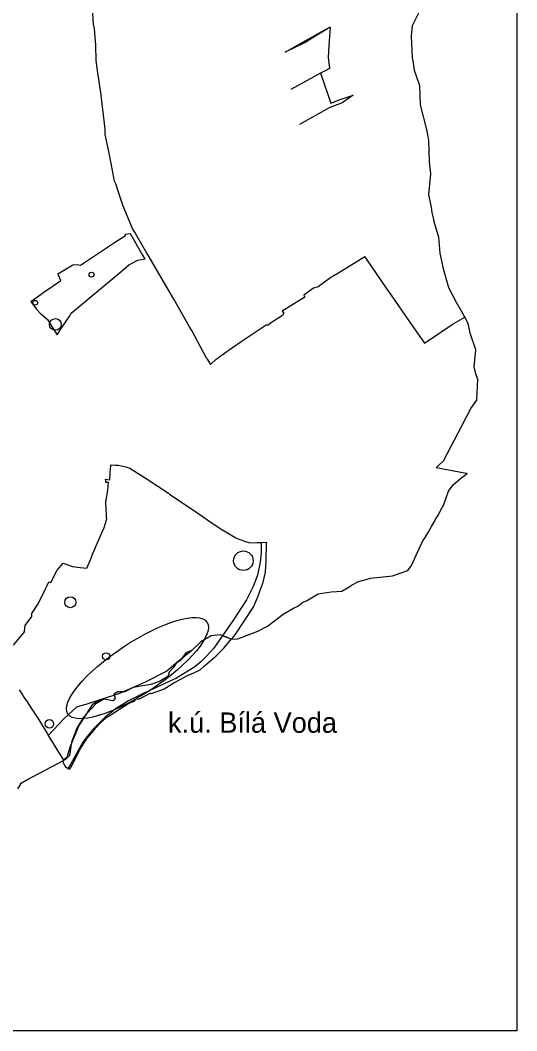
# Model space of a CAD drawing. Extents: x -581323 to -577255, y -1071205 to -1065973.
# Drawn here: x -578420 to -577319, y -1071165 to -1068923 of the extents above; entities that cross this region are included whole.
import ezdxf

# ---------------------------------------------------------------- set-up
doc = ezdxf.new("R2010")
doc.units = 0
for name, color, linetype in [('Budovy', 7, 'Continuous'), ('Hranice katastrálních území', 7, 'Continuous'), ('Lokality vhodné pro vodní komponenty', 7, 'Continuous'), ('Názvy KU', 7, 'Continuous'), ('Popis tisku', 7, 'Continuous'), ('Vnitřní obvod KoPÚ', 7, 'Continuous'), ('Vnější obvod_hranice převzatá z KoPÚ Bílá Voda', 7, 'Continuous'), ('Zbořeniště', 7, 'Continuous'), ('Šetření hranic v lesích', 7, 'Continuous'), ('Šetření řeky_potoky - linie', 7, 'Continuous'), ('Železnice - linie', 7, 'Continuous')]:
    doc.layers.add(name, color=color, linetype=linetype)

msp = doc.modelspace()

# ---------------------------------------------------------------- linework, layer by layer
at = {"layer": 'Budovy'}
for centre, radius in [((-578342.4, -1069598), 13), ((-577925.6, -1070122.3), 21.7), ((-578309.3, -1070214.4), 12.3), ((-578355.7, -1070484.1), 9.44)]:
    msp.add_circle(centre, radius, dxfattribs=at)
at = {"layer": 'Hranice katastrálních území'}
for p, q in [((-577427.3, -1069595.6), (-577434.8, -1069581.8)), ((-577422.8, -1069617.2), (-577427.3, -1069595.6)), ((-577410.1, -1069654.2), (-577422.8, -1069617.2)), ((-577413.8, -1069691.7), (-577410.1, -1069654.2)), ((-577410, -1069707.6), (-577413.8, -1069691.7)), ((-577405.3, -1069720.5), (-577410, -1069707.6)), ((-577408.1, -1069765.8), (-577405.3, -1069720.5)), ((-577421.1, -1069784.7), (-577408.1, -1069765.8)), ((-577441.9, -1069824.3), (-577421.1, -1069784.7)), ((-577457.3, -1069854.3), (-577441.9, -1069824.3)), ((-577482, -1069900.3), (-577457.3, -1069854.3)), ((-577498.4, -1069915.9), (-577496.9, -1069914.6)), ((-577435.3, -1069927.9), (-577498.4, -1069915.9)), ((-577496.9, -1069914.6), (-577491.3, -1069909.5)), ((-577491.3, -1069909.5), (-577482, -1069900.3)), ((-577443.9, -1069939.8), (-577429.1, -1069929.1)), ((-577429.1, -1069929.1), (-577435.3, -1069927.9)), ((-577470.7, -1069968.2), (-577460.2, -1069954)), ((-577460.2, -1069954), (-577443.9, -1069939.8)), ((-577481.4, -1069997.6), (-577476.1, -1069982.8)), ((-577476.1, -1069982.8), (-577470.7, -1069968.2)), ((-577493.9, -1070021.5), (-577484, -1070002.7)), ((-577484, -1070002.7), (-577481.4, -1069997.6)), ((-577500.2, -1070031.8), (-577493.9, -1070021.5)), ((-577516.1, -1070059.4), (-577508.4, -1070046.4)), ((-577508.4, -1070046.4), (-577502, -1070035)), ((-577502, -1070035), (-577500.2, -1070031.8)), ((-577527.7, -1070078), (-577522.6, -1070070.5)), ((-577522.6, -1070070.5), (-577516.1, -1070059.4)), ((-577538.9, -1070101.8), (-577533.8, -1070090.4)), ((-577533.8, -1070090.4), (-577527.7, -1070078)), ((-577552.9, -1070132.7), (-577538.9, -1070101.8)), ((-577560.7, -1070143.9), (-577552.9, -1070132.7)), ((-577650.8, -1070163.1), (-577643.8, -1070161)), ((-577643.8, -1070161), (-577594.8, -1070155.5)), ((-577594.8, -1070155.5), (-577560.7, -1070143.9)), ((-577707.6, -1070189.6), (-577689.6, -1070179.5)), ((-577689.6, -1070179.5), (-577685.8, -1070176.8)), ((-577685.8, -1070176.8), (-577670.5, -1070168.2)), ((-577670.5, -1070168.2), (-577650.8, -1070163.1)), ((-577785.6, -1070211.3), (-577759.8, -1070195.6)), ((-577759.8, -1070195.6), (-577731.1, -1070191.3)), ((-577731.1, -1070191.3), (-577707.6, -1070189.6)), ((-577837.2, -1070240.9), (-577814.4, -1070227.8)), ((-577814.4, -1070227.8), (-577805, -1070223.4)), ((-577805, -1070223.4), (-577793.8, -1070214.2)), ((-577793.8, -1070214.2), (-577785.6, -1070211.3)), ((-577872.3, -1070267.4), (-577837.2, -1070240.9)), ((-577893.5, -1070278.8), (-577872.3, -1070267.4)), ((-577997.3, -1070289.2), (-578019.6, -1070302.3)), ((-577976.7, -1070286.5), (-577997.3, -1070289.2)), ((-577964.6, -1070291.3), (-577976.7, -1070286.5)), ((-577952.3, -1070296.1), (-577964.6, -1070291.3)), ((-577952.3, -1070296.1), (-577938.2, -1070295.5)), ((-577938.2, -1070295.5), (-577893.5, -1070278.8)), ((-578019.6, -1070302.3), (-578039.5, -1070321.4)), ((-578059.7, -1070336.6), (-578067.1, -1070345.1)), ((-578053.3, -1070326.7), (-578059.7, -1070336.6)), ((-578039.5, -1070321.4), (-578053.3, -1070326.7)), ((-578081.2, -1070360.2), (-578090.1, -1070369.3)), ((-578074.5, -1070350), (-578081.2, -1070360.2)), ((-578067.1, -1070345.1), (-578074.5, -1070350)), ((-578093.1, -1070379.1), (-578111.9, -1070390.1)), ((-578090.1, -1070369.3), (-578093.1, -1070379.1)), ((-578169.9, -1070403.4), (-578188.6, -1070413)), ((-578148.2, -1070399.7), (-578169.9, -1070403.4)), ((-578130.5, -1070397.2), (-578148.2, -1070399.7)), ((-578111.9, -1070390.1), (-578130.5, -1070397.2)), ((-578234.8, -1070429.6), (-578253.1, -1070440)), ((-578214, -1070433.1), (-578234.8, -1070429.6)), ((-578209.5, -1070427.6), (-578214, -1070433.1)), ((-578203.9, -1070413.2), (-578212.6, -1070418.5)), ((-578212.6, -1070418.5), (-578209.5, -1070427.6)), ((-578188.6, -1070413), (-578203.9, -1070413.2)), ((-578253.1, -1070440), (-578279.9, -1070469.4)), ((-578279.9, -1070469.4), (-578294.7, -1070494)), ((-578294.7, -1070494), (-578306.8, -1070524.7)), ((-578306.8, -1070524.7), (-578311, -1070554.6)), ((-578405.8, -1070608.3), (-578324.5, -1070566)), ((-578321.1, -1070564.2), (-578324.5, -1070566)), ((-578311, -1070554.6), (-578321.1, -1070564.2)), ((-578420, -1070616.5), (-578405.8, -1070608.3)), ((-578425.8, -1070628.8), (-578418.8, -1070618.1)), ((-578418.8, -1070618.1), (-578420, -1070616.5))]:
    msp.add_line(p, q, dxfattribs=at)
at = {"layer": 'Lokality vhodné pro vodní komponenty'}
msp.add_ellipse((-578160.4, -1070360.7), major_axis=(154.1, 101.9), ratio=0.305974, dxfattribs=at)
at = {"layer": 'Popis tisku'}
msp.add_lwpolyline([(-581279.8, -1066020.1), (-577319.3, -1066020.1), (-577319.3, -1071165.4), (-581279.8, -1071165.4)], close=True, dxfattribs=at)
at = {"layer": 'Vnitřní obvod KoPÚ'}
for p, q in [((-578257.9, -1068932.3), (-578262.6, -1068862.3)), ((-578255.8, -1068942.2), (-578257.9, -1068932.3)), ((-578252.5, -1068978), (-578255.8, -1068942.2)), ((-578252.2, -1069012), (-578252.5, -1068978)), ((-578249.4, -1069034.4), (-578252.2, -1069012)), ((-578241.3, -1069083.9), (-578249.4, -1069034.4)), ((-578240.9, -1069087.1), (-578241.3, -1069083.9)), ((-578240.6, -1069089.6), (-578240.9, -1069087.1)), ((-578232.2, -1069164.5), (-578240.6, -1069089.6)), ((-578232.2, -1069176.7), (-578232.2, -1069164.5)), ((-578225, -1069210.3), (-578232.2, -1069176.7)), ((-578218.2, -1069244.6), (-578225, -1069210.3)), ((-578211.2, -1069280.1), (-578218.2, -1069244.6)), ((-578208.4, -1069286.3), (-578211.2, -1069280.1)), ((-578202.4, -1069304.4), (-578208.4, -1069286.3)), ((-578197, -1069320.3), (-578202.4, -1069304.4)), ((-578191.9, -1069335.6), (-578197, -1069320.3)), ((-578171.1, -1069385), (-578191.9, -1069335.6)), ((-578175.5, -1069396.7), (-578187.7, -1069398.6)), ((-578186.8, -1069400.8), (-578187.7, -1069398.6)), ((-578172.6, -1069402), (-578175.5, -1069396.7)), ((-578165.6, -1069394.7), (-578171.1, -1069385)), ((-578161.8, -1069401.3), (-578165.6, -1069394.7)), ((-578286.4, -1069466.5), (-578211.1, -1069416.5)), ((-578211.1, -1069416.5), (-578186.8, -1069400.8)), ((-578151.2, -1069440.2), (-578172.6, -1069402)), ((-578139.6, -1069440), (-578161.8, -1069401.3)), ((-578143.5, -1069452.4), (-578151.2, -1069440.2)), ((-578134.8, -1069448.3), (-578139.6, -1069440)), ((-578336.8, -1069485.4), (-578303.4, -1069466)), ((-578303.4, -1069466), (-578293.9, -1069464.9)), ((-578293.9, -1069464.9), (-578286.4, -1069466.5)), ((-578197.5, -1069481.1), (-578179.3, -1069465.9)), ((-578179.3, -1069465.9), (-578159.4, -1069455.5)), ((-578159.4, -1069455.5), (-578143.5, -1069452.4)), ((-578102.8, -1069502.9), (-578134.8, -1069448.3)), ((-577656.6, -1069447.7), (-577716.3, -1069484.9)), ((-577656.6, -1069447.7), (-577653.3, -1069452.6)), ((-577653.3, -1069452.6), (-577607.1, -1069519.5)), ((-578335.4, -1069488.9), (-578336.8, -1069485.4)), ((-578330.1, -1069500.5), (-578335.4, -1069488.9)), ((-578307.1, -1069572.9), (-578197.5, -1069481.1)), ((-577716.3, -1069484.9), (-577725.2, -1069490.4)), ((-578369.9, -1069527.9), (-578347.4, -1069512.4)), ((-578347.4, -1069512.4), (-578330.1, -1069500.5)), ((-578080.1, -1069541.9), (-578102.8, -1069502.9)), ((-577731.5, -1069494.1), (-577760, -1069514.2)), ((-577725.2, -1069490.4), (-577731.5, -1069494.1)), ((-578389.2, -1069541.8), (-578374, -1069530.7)), ((-578374, -1069530.7), (-578369.9, -1069527.9)), ((-577770.3, -1069517.7), (-577791.2, -1069533.2)), ((-577791.2, -1069533.2), (-577789, -1069537.2)), ((-577760, -1069514.2), (-577770.3, -1069517.7)), ((-577607.1, -1069519.5), (-577602.8, -1069525.7)), ((-577602.8, -1069525.7), (-577560.1, -1069587.6)), ((-578396.8, -1069547.3), (-578389.2, -1069541.8)), ((-578396.8, -1069547.3), (-578387.1, -1069560.6)), ((-578044.8, -1069603.4), (-578080.1, -1069541.9)), ((-577789, -1069537.2), (-577839.3, -1069568.8)), ((-578387.1, -1069560.6), (-578384, -1069564.4)), ((-578384, -1069564.4), (-578376.2, -1069573.1)), ((-578376.2, -1069573.1), (-578360.2, -1069587.3)), ((-578331.4, -1069609.5), (-578310.4, -1069578.7)), ((-578310.4, -1069578.7), (-578307.1, -1069572.9)), ((-577839, -1069578.5), (-577865.2, -1069595.5)), ((-577839.3, -1069568.8), (-577836.2, -1069573)), ((-577836.2, -1069573), (-577839, -1069578.5)), ((-578360.2, -1069587.3), (-578341.5, -1069616.9)), ((-577874.9, -1069599.7), (-577928.1, -1069634.8)), ((-577870.7, -1069599.3), (-577874.9, -1069599.7)), ((-577865.2, -1069595.5), (-577870.7, -1069599.3)), ((-577560.1, -1069587.6), (-577524.1, -1069639.7)), ((-577524.1, -1069639.7), (-577460.6, -1069596.6)), ((-577460.6, -1069596.6), (-577434.8, -1069581.8)), ((-578341.5, -1069616.9), (-578338.7, -1069621.4)), ((-578338.7, -1069621.4), (-578331.4, -1069609.5)), ((-578039.9, -1069611.8), (-578044.8, -1069603.4)), ((-578007, -1069672.7), (-578039.9, -1069611.8)), ((-577928.1, -1069634.8), (-577949.7, -1069649.9)), ((-577972.8, -1069665.9), (-577979.3, -1069670.4)), ((-577949.7, -1069649.9), (-577972.8, -1069665.9)), ((-578007, -1069672.7), (-578004.5, -1069677)), ((-578004.5, -1069677), (-577998.8, -1069687.1)), ((-577998.8, -1069687.1), (-577985.9, -1069674.8)), ((-577985.9, -1069674.8), (-577979.3, -1069670.4)), ((-578221.8, -1069943.1), (-578220, -1069916)), ((-578220, -1069916), (-578219.8, -1069913.3)), ((-578219.8, -1069913.3), (-578219.5, -1069909.8)), ((-578219.5, -1069909.8), (-578210.2, -1069910.3)), ((-578210.2, -1069910.3), (-578203.5, -1069910.6)), ((-578203.5, -1069910.6), (-578186.1, -1069913.9)), ((-578186.1, -1069913.9), (-578177.1, -1069916.9)), ((-578177.1, -1069916.9), (-578138.9, -1069941.1)), ((-578230.4, -1069944.1), (-578231.4, -1069941.2)), ((-578231.4, -1069941.2), (-578221.8, -1069943.1)), ((-578230.5, -1069948.7), (-578230.4, -1069944.1)), ((-578225, -1069949.1), (-578230.5, -1069948.7)), ((-578226, -1069966.2), (-578225, -1069949.1)), ((-578138.9, -1069941.1), (-578091.5, -1069972.5)), ((-578230.6, -1069991.4), (-578226, -1069966.2)), ((-578091.5, -1069972.5), (-578089.2, -1069974.5)), ((-578089.2, -1069974.5), (-578086.2, -1069976.5)), ((-578086.2, -1069976.5), (-578082.9, -1069978.7)), ((-578082.9, -1069978.7), (-578024.5, -1070018.6)), ((-578229.3, -1070021.8), (-578230.6, -1069991.4)), ((-578229, -1070025.5), (-578229.3, -1070021.8)), ((-578228.7, -1070029.4), (-578229, -1070025.5)), ((-578024.5, -1070018.6), (-577992.4, -1070040.6)), ((-578247.7, -1070079.1), (-578234.3, -1070048.6)), ((-578234.3, -1070048.6), (-578228.7, -1070029.4)), ((-577992.4, -1070040.6), (-577975.4, -1070051.5)), ((-577975.4, -1070051.5), (-577967.8, -1070056.3)), ((-577967.8, -1070056.3), (-577942.3, -1070071.3)), ((-577942.3, -1070071.3), (-577935.3, -1070074.3)), ((-578256.4, -1070099.6), (-578253.5, -1070092.8)), ((-578253.5, -1070092.8), (-578252.9, -1070090.7)), ((-578252.9, -1070090.7), (-578247.7, -1070079.1)), ((-577935.3, -1070074.3), (-577930.2, -1070076.1)), ((-577930.2, -1070076.1), (-577925.3, -1070078.1)), ((-577925.3, -1070078.1), (-577921.1, -1070079.8)), ((-577921.1, -1070079.8), (-577911.3, -1070082.4)), ((-577911.3, -1070082.4), (-577894.9, -1070082.2)), ((-577894.9, -1070082.2), (-577887.3, -1070081.8)), ((-577887.3, -1070081.8), (-577874.6, -1070081.4)), ((-577874.7, -1070084.8), (-577875.4, -1070122.8)), ((-577874.6, -1070082.6), (-577874.7, -1070084.8)), ((-577874.6, -1070081.4), (-577874.6, -1070082.6)), ((-578272.5, -1070139.2), (-578263.3, -1070116.9)), ((-578263.3, -1070116.9), (-578259.8, -1070107.5)), ((-578259.8, -1070107.5), (-578256.4, -1070099.6)), ((-578338.8, -1070143.4), (-578328.3, -1070131.4)), ((-578328.3, -1070131.4), (-578325.1, -1070127.8)), ((-578325.1, -1070127.8), (-578304.4, -1070134.9)), ((-578304.4, -1070134.9), (-578287.5, -1070137.2)), ((-578287.5, -1070137.2), (-578272.5, -1070139.2)), ((-577875.4, -1070122.8), (-577877.6, -1070148)), ((-578352.5, -1070170.9), (-578338.8, -1070143.4)), ((-577877.6, -1070148), (-577883, -1070172.8)), ((-578380.3, -1070218.3), (-578363.4, -1070183)), ((-578363.4, -1070183), (-578361.3, -1070178.7)), ((-578361.3, -1070178.7), (-578356.6, -1070168.8)), ((-578356.6, -1070168.8), (-578352.5, -1070170.9)), ((-577883, -1070172.8), (-577889.7, -1070190.4)), ((-577894.3, -1070203.5), (-577903, -1070223.6)), ((-577889.7, -1070190.4), (-577894.3, -1070203.5)), ((-578394.9, -1070239.7), (-578380.3, -1070218.3)), ((-577903, -1070223.6), (-577944.7, -1070286.7)), ((-578409.6, -1070265.8), (-578394.9, -1070246)), ((-578394.9, -1070246), (-578394.9, -1070239.7)), ((-578410.8, -1070279.7), (-578409.6, -1070265.8)), ((-578410.8, -1070279.7), (-578436.2, -1070309.9)), ((-577950.7, -1070294.2), (-577952.3, -1070296.1)), ((-577944.7, -1070286.7), (-577950.7, -1070294.2)), ((-578056.5, -1070381.1), (-578077.7, -1070392.7)), ((-578051.8, -1070378.8), (-578056.5, -1070381.1)), ((-578043.7, -1070375), (-578051.8, -1070378.8)), ((-578422.5, -1070408.6), (-578415.7, -1070419.6)), ((-578101, -1070407.1), (-578130.4, -1070418)), ((-578077.7, -1070392.7), (-578101, -1070407.1)), ((-578415.7, -1070419.6), (-578412.4, -1070424.9)), ((-578412.4, -1070424.9), (-578405.1, -1070435.2)), ((-578163.7, -1070430.3), (-578168.3, -1070434.8)), ((-578156.9, -1070429.2), (-578163.7, -1070430.3)), ((-578131.8, -1070416.3), (-578156.9, -1070429.2)), ((-578130.4, -1070418), (-578131.8, -1070416.3)), ((-578405.1, -1070435.2), (-578394.4, -1070451.5)), ((-578394.4, -1070451.5), (-578381.2, -1070471.6)), ((-578179.7, -1070439), (-578223.4, -1070467)), ((-578168.3, -1070434.8), (-578179.7, -1070439)), ((-578381.2, -1070471.6), (-578361.7, -1070504.2)), ((-578229.6, -1070471), (-578243.8, -1070483.9)), ((-578223.4, -1070467), (-578229.6, -1070471)), ((-578258, -1070499.1), (-578273, -1070516.4)), ((-578243.8, -1070483.9), (-578258, -1070499.1)), ((-578361.7, -1070504.2), (-578359.8, -1070506.5)), ((-578359.8, -1070506.5), (-578358.3, -1070509.9)), ((-578358.3, -1070509.9), (-578324.2, -1070565.1)), ((-578273, -1070516.4), (-578284.4, -1070534.6)), ((-578284.4, -1070534.6), (-578293.1, -1070550.7)), ((-578324.2, -1070565.1), (-578325.7, -1070569.5)), ((-578299.4, -1070563.7), (-578305.9, -1070575.8)), ((-578293.1, -1070550.7), (-578299.4, -1070563.7)), ((-578325.7, -1070569.5), (-578319.8, -1070580)), ((-578319.8, -1070580), (-578310.8, -1070585.2)), ((-578305.9, -1070575.8), (-578310.8, -1070585.2))]:
    msp.add_line(p, q, dxfattribs=at)
at = {"layer": 'Vnější obvod_hranice převzatá z KoPÚ Bílá Voda'}
for p, q in [((-577532.8, -1068898.4), (-577551.4, -1068935)), ((-577551.4, -1068935), (-577553.3, -1068958.5)), ((-577553.3, -1068958.5), (-577551.1, -1069006.4)), ((-577551.1, -1069006.4), (-577550.1, -1069012.7)), ((-577550.1, -1069012.7), (-577546.8, -1069033.8)), ((-577546.8, -1069033.8), (-577535.7, -1069065.3)), ((-577535.7, -1069065.3), (-577535, -1069069.4)), ((-577535, -1069069.4), (-577533.6, -1069110.4)), ((-577533.6, -1069110.4), (-577519.8, -1069165.7)), ((-577519.8, -1069165.7), (-577514.7, -1069189.4)), ((-577514.7, -1069189.4), (-577513.5, -1069237.4)), ((-577513.5, -1069237.4), (-577510.8, -1069263.6)), ((-577510.8, -1069263.6), (-577514.9, -1069309.4)), ((-577514.9, -1069309.4), (-577509.2, -1069338.8)), ((-577509.2, -1069338.8), (-577507.5, -1069349.4)), ((-577507.5, -1069349.4), (-577503.1, -1069368.2)), ((-577491.9, -1069404.2), (-577503.1, -1069368.2)), ((-577489.5, -1069439.8), (-577491.9, -1069404.2)), ((-577480.7, -1069477.2), (-577489.5, -1069439.8)), ((-577469.6, -1069516.5), (-577480.7, -1069477.2)), ((-577452.8, -1069549.3), (-577469.6, -1069516.5)), ((-577442.1, -1069568.6), (-577452.8, -1069549.3)), ((-577434.8, -1069581.8), (-577442.1, -1069568.6)), ((-577954, -1070298.3), (-577952.3, -1070296.1)), ((-577986.1, -1070333.5), (-577969.3, -1070317)), ((-577969.3, -1070317), (-577954, -1070298.3)), ((-578011.6, -1070355.7), (-577986.1, -1070333.5)), ((-578043.7, -1070375), (-578021.6, -1070364.5)), ((-578021.6, -1070364.5), (-578011.6, -1070355.7))]:
    msp.add_line(p, q, dxfattribs=at)
at = {"layer": 'Zbořeniště'}
for centre, radius in [((-578262.2, -1069487.6), 5.42), ((-578387.1, -1069550), 5.25), ((-578229.8, -1070334.4), 7.93)]:
    msp.add_circle(centre, radius, dxfattribs=at)
at = {"layer": 'Šetření hranic v lesích'}
for p, q in [((-577788.3, -1068968.6), (-577744.9, -1068944.3)), ((-577733.2, -1068938.1), (-577788.2, -1068972.7)), ((-577744.9, -1068944.3), (-577733.2, -1068938.1)), ((-577733.2, -1068938.1), (-577736, -1068979.6)), ((-577832.9, -1068994), (-577788.3, -1068968.6)), ((-577788.2, -1068972.7), (-577832.9, -1068994)), ((-577736, -1068979.6), (-577737.7, -1069005.5)), ((-577737.7, -1069005.5), (-577734.5, -1069029.9)), ((-577754.2, -1069040.7), (-577820.5, -1069077)), ((-577744.2, -1069035.3), (-577754.2, -1069040.7)), ((-577754.2, -1069040.7), (-577731.6, -1069107.1)), ((-577734.5, -1069029.9), (-577744.2, -1069035.3)), ((-577706.7, -1069106), (-577735.4, -1069117.4)), ((-577731.6, -1069107.1), (-577710.9, -1069099)), ((-577710.9, -1069099), (-577682.2, -1069089.2)), ((-577682.2, -1069089.2), (-577706.7, -1069106)), ((-577735.4, -1069117.4), (-577801.1, -1069154.4))]:
    msp.add_line(p, q, dxfattribs=at)
at = {"layer": 'Šetření řeky_potoky - linie'}
for p, q in [((-577997.3, -1070289.2), (-578019.6, -1070302.3)), ((-577976.7, -1070286.5), (-577997.3, -1070289.2)), ((-577952.3, -1070296.1), (-577976.7, -1070286.5)), ((-578019.6, -1070302.3), (-578039.5, -1070321.4)), ((-578039.5, -1070321.4), (-578074.5, -1070350)), ((-578074.5, -1070350), (-578095.4, -1070367.1)), ((-578095.4, -1070367.1), (-578145.1, -1070392.2)), ((-578145.1, -1070392.2), (-578200.1, -1070416.6)), ((-578243.3, -1070431), (-578272.9, -1070440.4)), ((-578243.3, -1070431), (-578260.9, -1070441.9)), ((-578200.1, -1070416.6), (-578243.3, -1070431)), ((-578295.4, -1070447.4), (-578323, -1070472.5)), ((-578272.9, -1070440.4), (-578295.4, -1070447.4)), ((-578260.9, -1070441.9), (-578290.5, -1070488.1)), ((-578323, -1070472.5), (-578358.3, -1070509.9)), ((-578290.5, -1070488.1), (-578310, -1070534.9)), ((-578310, -1070534.9), (-578316.7, -1070559.3)), ((-578316.7, -1070559.3), (-578324.2, -1070565.1))]:
    msp.add_line(p, q, dxfattribs=at)
at = {"layer": 'Železnice - linie'}
for p, q in [((-577886.1, -1070081.7), (-577886.1, -1070104.5)), ((-577886.1, -1070104.5), (-577888.2, -1070125.2)), ((-577888.2, -1070125.2), (-577894.6, -1070154.1)), ((-577894.6, -1070154.1), (-577903.7, -1070179.5)), ((-577903.7, -1070179.5), (-577919, -1070208.8)), ((-577931, -1070228.7), (-577949, -1070255.6)), ((-577919, -1070208.8), (-577931, -1070228.7)), ((-577949, -1070255.6), (-577991.4, -1070316.1)), ((-577991.4, -1070316.1), (-578007.3, -1070334.3)), ((-578007.3, -1070334.3), (-578019.6, -1070346.4)), ((-578032.9, -1070357.5), (-578074.1, -1070383.3)), ((-578019.6, -1070346.4), (-578032.9, -1070357.5)), ((-578074.1, -1070383.3), (-578149.2, -1070417.6)), ((-578149.2, -1070417.6), (-578180, -1070432.9)), ((-578207.9, -1070450.5), (-578232.1, -1070469.8)), ((-578180, -1070432.9), (-578207.9, -1070450.5)), ((-578232.1, -1070469.8), (-578257.9, -1070495.5)), ((-578257.9, -1070495.5), (-578271.2, -1070511.3)), ((-578308.5, -1070572.7), (-578313.9, -1070583.4))]:
    msp.add_line(p, q, dxfattribs=at)
msp.add_lwpolyline([(-578271.2, -1070511.3), (-578281.3, -1070525), (-578308.5, -1070572.7)], dxfattribs=at)

# ---------------------------------------------------------------- texts
at = {"layer": 'Názvy KU'}
msp.add_text('k.ú. Bílá Voda', height=45, dxfattribs=at).set_placement((-578092.7, -1070504.1))

doc.saveas('drawing.dxf')
